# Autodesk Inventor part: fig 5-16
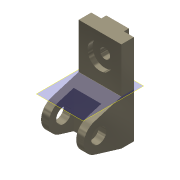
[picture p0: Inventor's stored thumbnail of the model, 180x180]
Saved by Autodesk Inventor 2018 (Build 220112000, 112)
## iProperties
Shininess: 65.0
Angle Display Precision: 2
Document Length Units: 11269
Document Angle Units: 11279
Document Time Units: 11290
Document Mass Units: 11283
Document Length Units Precision: 3
Document Angle Units Precision: 2
Compacted: False
Created: 2001-11
Part Number: fig 5-16
Document SubType Name: Modeling
Designer: Renu Muthoo
Density: 1 g/cm^3
Material: Generic
Appearance: Metal-Titanium (Polished)
Density: 0.0
Volumn: 0.0
Area: 0.0
PropertySet Name: Model Information
Control State: 0
Master: False
Checked Out: False
Author: Renu Muthoo
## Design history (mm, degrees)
node "Sketch1"
sketch "Sketch2"
  geometry: L1 (33.257, 104.664)-(33.257, -75.336); L2 (33.257, -75.336)-(8.257, -75.336); L3 (8.257, -75.336)-(-45.451, -59.045); L4 (-45.451, -1.628)-(8.257, 14.664); L5 (8.257, 14.664)-(8.257, 104.664); L6 (8.257, 104.664)-(33.257, 104.664); C1 r 15 at (-36.743, -30.336); A1 r 30 centre (-36.743, -30.336) between (-45.451, -1.628) and (-45.451, -59.045)
  constraints: 12 end point, 2 centre point, 2 equal length, 2 parallel, 2 point on circle, 2 tangent, 1 coincident, 1 perpendicular, 1 vertical
  dimensions: "d0" = 180 distance of L1.start L1.end; "d1" = 30 radius of A1; "d2" = 25 distance of L5.end L1.start; "d3" = 45 distance from line of L2 A1.centre; "d4" = 70 distance from line of L1 A1.centre; "d5" = 30 diameter of C1
extrude "Extrusion1" new body sketch "Sketch2" distance "d6" = 85; taper "d7" = 0 deg
workplane "Work Plane1"
sketch "Sketch3"
  geometry: L1 (15, 62.364)-(70, 62.364); L2 (70, 62.364)-(70, -52.386); L3 (70, -52.386)-(15, -52.386); L4 (15, -52.386)-(15, 62.364); L5 (0, -45)-(0, -28.708) reference
  constraints: 8 end point, 2 parallel, 1 horizontal, 1 perpendicular
  dimensions: "d8" = 55 distance of L1.start L1.end; "d9" = 15 distance between parallel lines of L5 L4
extrude "Extrusion2" cut sketch "Sketch3" distance "d10" = 50; taper "d11" = 0 deg
sketch "Sketch4"
  geometry: L1 (0, 25)-(85, 25) reference; L2 (0, 0)-(0, 25) reference; L3 (20, 25)-(65, 25); L4 (65, 25)-(65, 35); L5 (65, 35)-(20, 35); L6 (20, 35)-(20, 25)
  constraints: 8 end point, 2 parallel, 1 horizontal, 1 perpendicular, 1 point on line
  dimensions: "d12" = 45 distance of L4.end L5.end; "d13" = 10 distance of L3.end L4.end; "d14" = 20 distance between parallel lines of L2 L6
extrude "Extrusion3" join sketch "Sketch4" stored distance "d15" = 50; taper "d16" = 0 deg
sketch "Sketch5"
  geometry: L1 (85, 0)-(85, 90) reference; L2 (0, 90)-(85, 90) reference; 1 further point
  dimensions: "d17" = 42 distance from line of L2 point (42.5, 48); "d18" = 42.5 distance from line of L1 point (42.5, 48)
hole "Hole1" sketch "Sketch5" at (42.5, 48) diameter "d19" = 20; stored, may be unused: countersink angle "d23" = 82 deg, drill point angle "d25" = 118 deg; dims "d20" = 6, "d21" = 50, "d22" = 10, "d24" = 8
workplane "Work Plane7"
body "Solid1"
other parameters: "d27" = 90 deg
